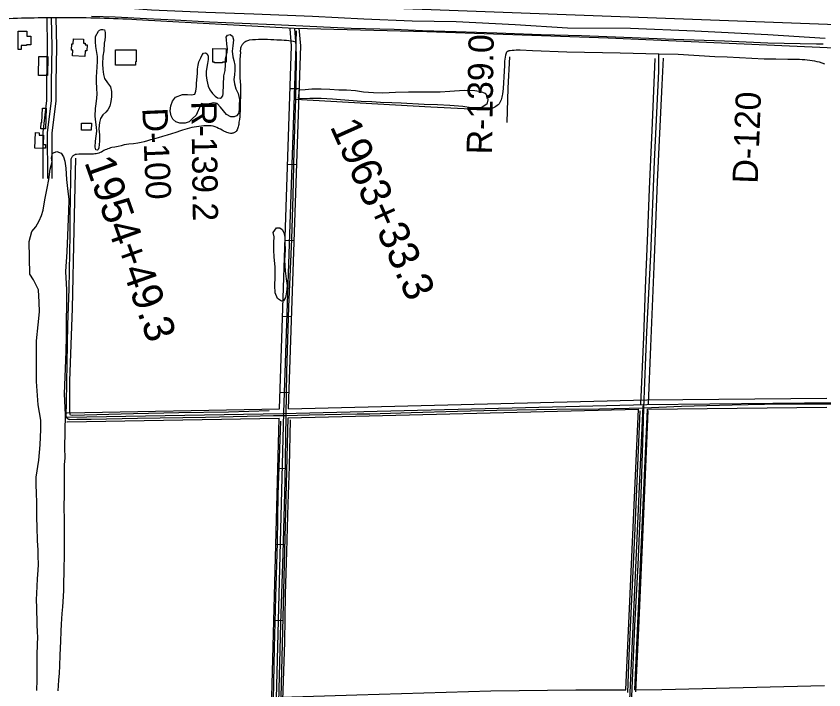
# Model space of a CAD drawing. Extents: x 3508733 to 3546731, y 546897 to 572481.
# Drawn here: x 3519217 to 3521873, y 561066 to 563281 of the extents above; entities that cross this region are included whole.
import ezdxf

# ---------------------------------------------------------------- set-up
doc = ezdxf.new("R2010")
doc.units = 0
for name, color, linetype in [('V-BLDG-OTLN', 7, 'Continuous'), ('V-DTCH-CNTR', 7, 'Continuous'), ('V-LEVE-TOET', 7, 'Continuous'), ('V-RIVR-RANG-IDEN', 7, 'Continuous'), ('V-ROAD-CNTR', 7, 'Continuous'), ('V-SITE-VEGE', 7, 'Continuous'), ('V-SURV-IDEN', 7, 'Continuous'), ('V-SURV-LINE', 7, 'Continuous'), ('V-TOPO-SHOR', 7, 'Continuous')]:
    doc.layers.add(name, color=color, linetype=linetype)

msp = doc.modelspace()

# ---------------------------------------------------------------- linework, layer by layer
at = {"layer": 'V-BLDG-OTLN'}
for points in [[(3519223.6, 563232.1), (3519252.1, 563232.1), (3519252.1, 563215.9), (3519265.8, 563215.9), (3519265.9, 563186.9), (3519251.6, 563186.8), (3519251.6, 563184.8), (3519233.9, 563184.7), (3519233.9, 563171.9), (3519223.7, 563171.9)], [(3519405.9, 563207.3), (3519438.8, 563205.9), (3519438.3, 563192.5), (3519444.3, 563192.3), (3519444.1, 563187.3), (3519450.4, 563187.1), (3519449.6, 563167.4), (3519443.8, 563167.6), (3519443, 563148.8), (3519402.9, 563150.4), (3519403.7, 563169.1), (3519399.4, 563169.3), (3519400.3, 563190.6), (3519405.2, 563190.4)], [(3519544.4, 563170.9), (3519611.7, 563170.9), (3519611.7, 563130.9), (3519609.8, 563130.9), (3519609.8, 563120.7), (3519544.4, 563120.7)], [(3519864.6, 563174.7), (3519908.4, 563174.2), (3519907.9, 563130.1), (3519896.1, 563130.2), (3519896.1, 563127.5), (3519869.2, 563127.8), (3519869.2, 563130.3), (3519864.1, 563130.4)], [(3519321.8, 563148.4), (3519320.7, 563086.2), (3519290.7, 563086.7), (3519291.8, 563148.9)], [(3519316.5, 562978.3), (3519314.1, 562910.8), (3519298.5, 562911.3), (3519299.2, 562931.6), (3519301.9, 562931.5), (3519303.5, 562978.7)], [(3519464.4, 562906.3), (3519432.2, 562906.7), (3519432.5, 562929.5), (3519464.7, 562929.1)], [(3519307.6, 562890.1), (3519306.7, 562859.1), (3519313.7, 562858.9), (3519313.4, 562847.1), (3519307.2, 562847.2), (3519307.2, 562846.1), (3519278.9, 562847), (3519280.5, 562898.2), (3519293.5, 562897.8), (3519293.3, 562890.5)]]:
    msp.add_lwpolyline(points, close=True, dxfattribs=at)
at = {"layer": 'V-DTCH-CNTR'}
for points in [[(3520138.2, 563233.1), (3520137.4, 563196.2), (3520138.4, 563133), (3520135.5, 563007.3)], [(3520137.4, 563196.2), (3520129.6, 563197.7), (3520121.8, 563199), (3520114, 563200.1), (3520106.1, 563200.9), (3520098.2, 563201.6), (3520090.4, 563202.1), (3520082.4, 563202.4), (3520074.5, 563202.4), (3520064.5, 563203.3), (3520054.5, 563204), (3520044.4, 563204.4), (3520034.3, 563204.6), (3520024.2, 563204.6), (3520014.2, 563204.3), (3520004.1, 563203.8), (3519994.1, 563203.1), (3519984, 563202.1), (3519981, 563201.3), (3519978.1, 563200.3), (3519975.2, 563199.1), (3519972.5, 563197.7), (3519969.8, 563196.1), (3519967.3, 563194.3), (3519964.9, 563192.3), (3519963, 563190.4), (3519961.3, 563188.3), (3519959.8, 563186.1), (3519958.5, 563183.8), (3519957.3, 563181.4), (3519956.3, 563178.9), (3519955.6, 563176.3), (3519955, 563173.7), (3519954.6, 563171.1), (3519954.4, 563168.4), (3519954.4, 563165.8), (3519954.7, 563163.1), (3519953.8, 563151), (3519953.2, 563138.9), (3519952.8, 563126.7), (3519952.5, 563114.6), (3519952.5, 563102.5), (3519952.7, 563090.3), (3519953.2, 563078.2), (3519953.8, 563066.1), (3519954.6, 563053.9), (3519955, 563038.1)], [(3521877, 563123.7), (3521868.3, 563126.7), (3521859.5, 563129.5), (3521851.4, 563131.4), (3521843.3, 563133.1), (3521835.1, 563134.5), (3521826.9, 563135.7), (3521818.7, 563136.7), (3521810.4, 563137.4), (3521802.2, 563138), (3521793.9, 563138.3), (3521755, 563138.9), (3521716.1, 563139.5), (3521677.3, 563139.9), (3521636.7, 563142.2), (3521596, 563144.3), (3521555.4, 563146.1), (3521514.7, 563147.7), (3521394.8, 563154.8), (3521331.3, 563155.9), (3521203.7, 563159.1), (3521027.9, 563162.9), (3520915.8, 563167.1), (3520874.8, 563169.2), (3520868.1, 563169.3), (3520861.4, 563169.3), (3520854.7, 563168.9), (3520848.1, 563168.3), (3520841.4, 563167.4), (3520839.6, 563167.3), (3520837.9, 563166.9), (3520836.2, 563166.4), (3520834.6, 563165.7), (3520833, 563164.7), (3520831.6, 563163.6), (3520830.4, 563162.4), (3520829.2, 563161), (3520828.3, 563159.4), (3520826.8, 563152.8), (3520825.5, 563146.2), (3520824.5, 563139.5), (3520823.8, 563132.8), (3520823.3, 563126), (3520823.1, 563119.2), (3520822.4, 563100.4), (3520821.4, 563081.5), (3520820.1, 563062.6), (3520818.6, 563043.8), (3520816.9, 563025), (3520816, 563020.2), (3520814.8, 563015.4), (3520813.4, 563010.7), (3520811.8, 563006.1), (3520809.9, 563001.5)], [(3521200.8, 560109.6), (3521206.1, 560234.8), (3521216.6, 560444), (3521225.9, 560642.9), (3521237.8, 560889.6), (3521242.3, 561044), (3521252.2, 561275.9), (3521262.4, 561476.9), (3521272.7, 561708.7), (3521279.4, 561913.5), (3521281.7, 561993.5), (3521291.8, 562243.4), (3521304.1, 562496.8), (3521316.7, 562803), (3521330.9, 563100.5), (3521331.3, 563155.9)], [(3519955, 563038.1), (3519954.3, 562978.7), (3519953.9, 562969.4), (3519953.4, 562960.2), (3519952.5, 562950.9), (3519951.5, 562941.7), (3519950.2, 562932.5), (3519949.9, 562928.8), (3519949.4, 562925.1), (3519948.7, 562921.4), (3519947.8, 562917.8), (3519946.7, 562914.3), (3519945.3, 562910.8), (3519943.8, 562907.4), (3519942, 562904.1), (3519940.6, 562902.4), (3519939, 562900.9), (3519937.2, 562899.6), (3519935.4, 562898.4), (3519933.4, 562897.4), (3519931.3, 562896.7), (3519929.2, 562896.1), (3519927, 562895.7), (3519924.8, 562895.6), (3519922.6, 562895.6), (3519918.4, 562896.5), (3519914.3, 562897.6), (3519910.2, 562899), (3519906.2, 562900.6), (3519902.3, 562902.4), (3519898.5, 562904.5), (3519894.8, 562906.8), (3519889.1, 562909.7), (3519883.3, 562912.4), (3519877.4, 562914.9), (3519871.4, 562917.1), (3519865.4, 562919.2), (3519859.2, 562921), (3519851, 562921), (3519842.8, 562920.9), (3519834.6, 562920.4), (3519826.4, 562919.8), (3519818.3, 562918.9), (3519810.5, 562917.9), (3519802.7, 562916.6), (3519795.1, 562915.1), (3519787.4, 562913.3), (3519779.8, 562911.3), (3519772.3, 562909.1), (3519764.9, 562906.6), (3519757.5, 562903.8), (3519743, 562898.9), (3519728.4, 562894.2), (3519713.8, 562889.6), (3519699.1, 562885.3), (3519684.3, 562881.2), (3519669.5, 562877.3)], [(3520135.5, 563007.3), (3520134.9, 562981.2), (3520130.4, 562840.1), (3520126.7, 562690.3), (3520122.7, 562548), (3520113.1, 562325.6), (3520106.9, 562112), (3520103.9, 561967.9), (3520100.4, 561752.6), (3520094.1, 561512.8), (3520087, 561283.7), (3520079.7, 561024)], [(3520770.5, 562973.9), (3520756.9, 562973.6), (3520581.2, 562981.7), (3520135.5, 563007.3)], [(3520809.9, 563001.5), (3520807.8, 562997.1), (3520805.5, 562992.7), (3520802.2, 562989.9), (3520798.8, 562987.1), (3520795.2, 562984.6), (3520791.5, 562982.3), (3520787.6, 562980.2), (3520783.7, 562978.3), (3520779.7, 562976.7), (3520775.5, 562975.2), (3520771.3, 562974), (3520770.5, 562973.9)], [(3519669.5, 562877.3), (3519659.3, 562874.1), (3519649, 562871.1), (3519638.7, 562868.4), (3519628.3, 562865.9), (3519617.8, 562863.7), (3519602.9, 562862), (3519587.9, 562860), (3519573.1, 562857.8), (3519562.8, 562855.2), (3519552.5, 562852.9), (3519542.1, 562850.8), (3519531.7, 562849), (3519527.2, 562847.9), (3519522.8, 562846.6), (3519518.5, 562845), (3519514.2, 562843.3), (3519510.1, 562841.3), (3519506, 562839.2), (3519502.1, 562836.8), (3519498.2, 562834.2), (3519493.9, 562832.6), (3519489.5, 562831.1), (3519485, 562829.9), (3519480.5, 562828.9), (3519475.9, 562828.1), (3519471.3, 562827.6), (3519466.7, 562827.2), (3519462, 562827.1), (3519457.4, 562827.3), (3519452.7, 562827.7), (3519445.4, 562828)], [(3519415.9, 562826.5), (3519413.9, 562826.4), (3519411.8, 562826), (3519409.8, 562825.4), (3519407.9, 562824.6), (3519406.1, 562823.6), (3519404.5, 562822.3), (3519402.9, 562820.8), (3519401.4, 562819.1), (3519400.2, 562817.3), (3519399.1, 562815.4), (3519398.2, 562813.4), (3519397.5, 562811.3), (3519397.1, 562809.1), (3519396.8, 562806.9), (3519395.7, 562745.2), (3519394.8, 562683.5), (3519394.1, 562621.8), (3519393.5, 562562.5), (3519392.6, 562503.3), (3519391.5, 562444), (3519390.1, 562384.8), (3519388.5, 562325.5), (3519386.7, 562266.3)], [(3519445.4, 562828), (3519438, 562828), (3519430.6, 562827.8), (3519423.3, 562827.3), (3519415.9, 562826.5)], [(3519386.7, 562266.3), (3519381.6, 562012.3), (3519380.9, 561966), (3519381.3, 561964.3), (3519382, 561962.7), (3519382.9, 561961.2), (3519383.9, 561959.9), (3519385.1, 561958.6), (3519386.5, 561957.6), (3519388, 561956.7), (3519389.5, 561956), (3519391.2, 561955.5), (3519392.9, 561955.3), (3519416.6, 561955.7), (3519440.4, 561955.8), (3519464.1, 561955.6), (3519615.9, 561959.2), (3519839.6, 561962.7), (3519977.4, 561965.6), (3520063.3, 561968.5), (3520103.9, 561967.9)], [(3520103.9, 561967.9), (3520181.4, 561970.3), (3520338.6, 561973.6), (3520380.4, 561973.3), (3520515.9, 561977.7), (3520668.2, 561982), (3520798.5, 561985.6), (3520993.9, 561989.2), (3521135.9, 561989.5), (3521281.7, 561993.5), (3521405.1, 561999.2), (3521571.5, 562003.1), (3521731.1, 562006.2), (3521902.6, 562006.1)]]:
    msp.add_lwpolyline(points, dxfattribs=at)
at = {"layer": 'V-LEVE-TOET'}
msp.add_lwpolyline([(3521877.3, 563208), (3521689.6, 563219.8), (3521449.1, 563231.9), (3521238, 563240.3), (3521030.7, 563241.6), (3520858.9, 563253.2), (3520664.7, 563263.2), (3520520, 563264.6), (3520360.8, 563271.9), (3520191.5, 563280.1), (3519999.1, 563288), (3519841.5, 563293.5), (3519662, 563301.5), (3519578.4, 563307.7), (3519455.1, 563312.4), (3519315.4, 563322.4), (3519199.5, 563317.2)], dxfattribs=at)
at = {"layer": 'V-ROAD-CNTR'}
for p, q in [((3520118.4, 563043.9), (3520148.4, 563042.9)), ((3520110, 562794.1), (3520140, 562793.1)), ((3520101.7, 562544.2), (3520131.7, 562543.2)), ((3520093.3, 562294.3), (3520123.3, 562293.3)), ((3520084.9, 562044.5), (3520114.9, 562043.5)), ((3520078, 561794.5), (3520108, 561793.7)), ((3520071.6, 561544.5), (3520101.6, 561543.8)), ((3520065.2, 561294.6), (3520095.2, 561293.9))]:
    msp.add_line(p, q, dxfattribs=at)
for points in [[(3519317.9, 563275.5), (3519319.9, 563181.1), (3519317.6, 563062.2), (3519317.4, 563003.7), (3519304.7, 562899.4), (3519305.1, 562747.6)], [(3519332.9, 563275.8), (3519334.9, 563181.2), (3519332.6, 563062.1), (3519332.4, 563002.8), (3519319.7, 562898.5), (3519320.1, 562747.6)], [(3519347.9, 563276.1), (3519349.9, 563181.2), (3519347.6, 563061.9), (3519347.4, 563001.9), (3519334.7, 562897.6), (3519335.1, 562747.7)], [(3523486.8, 563119.6), (3523364.6, 563119.4), (3522668.4, 563145.9), (3522135.8, 563169), (3521909.5, 563175.7), (3521163.8, 563208.5), (3520567.9, 563230), (3520131.3, 563241.1), (3519612.9, 563269.3)], [(3519967.4, 557245.9), (3519997.9, 558160.3), (3520022.3, 559134.5), (3520051.5, 560082.9), (3520073.6, 561037.4), (3520097.7, 561978.1), (3520138.1, 563183.8), (3520133.3, 563241.1)], [(3520083.1, 561989.6), (3520123.1, 563183.4), (3520118.4, 563239.8)], [(3520113.2, 561990.3), (3520153.1, 563184.2), (3520148.2, 563242.3)], [(3519383.9, 561962.3), (3519385.1, 561962.4), (3520094.7, 561974.8), (3521291.5, 562004.2), (3521912.4, 562010.4), (3522605.1, 562030.9)], [(3520113.2, 561990.3), (3521291.2, 562019.2), (3521883.4, 562025.1)], [(3521192.5, 560127.6), (3521202.3, 560314.9), (3521236.7, 561056.2), (3521279.5, 562000.2)], [(3519383.4, 561977.3), (3519384.7, 561977.3), (3520083.1, 561989.6)], [(3520112.3, 561960.3), (3521263.9, 561988.5)], [(3521222.2, 561066.2), (3521263.9, 561988.5)], [(3521252.2, 561066.3), (3521294, 561989.2)], [(3521294, 561989.2), (3521883.2, 561995.1)], [(3519384.3, 561947.3), (3519385.4, 561947.4), (3520082.3, 561959.6)], [(3520058.7, 561042.1), (3520082.3, 561959.6)], [(3520088.7, 561042.2), (3520112.3, 561960.3)], [(3521252.2, 561066.3), (3521340.4, 561066.5), (3521875.7, 561080.2)], [(3520088.7, 561042.2), (3520337.5, 561049.5), (3520778.3, 561062.5), (3521058, 561065.7), (3521222.2, 561066.2)]]:
    msp.add_lwpolyline(points, dxfattribs=at)
for centre, radius, start, end in [((3519354.7, 558597.9), 4677.9, 89.7771, 92.4746), ((3519394.4, 559639.2), 3636.6, 86.5559, 90.338)]:
    msp.add_arc(centre, radius, start, end, dxfattribs=at)
at = {"layer": 'V-SITE-VEGE'}
for points in [[(3519487.7, 563231.8), (3519491.6, 563235.6), (3519497.4, 563237.5), (3519502.5, 563237.9), (3519507.6, 563235.9), (3519509.9, 563227.9), (3519510, 563214.4), (3519508.6, 563202.1), (3519507.3, 563192), (3519505.3, 563167.8), (3519502.5, 563150), (3519501, 563123.9), (3519502.4, 563106.5), (3519504.9, 563089.4), (3519508.4, 563076.5), (3519517.6, 563062.4), (3519527.4, 563049.3), (3519530.8, 563033.8), (3519530.4, 563016.1), (3519528.8, 563000.2), (3519525, 562985.5), (3519518.8, 562973.5), (3519512.2, 562965.2), (3519502.7, 562956.3), (3519495, 562945.3), (3519491.3, 562931.3), (3519489.8, 562910.3), (3519491, 562890.8), (3519492, 562870.2), (3519489.3, 562848.5), (3519487.1, 562842.5), (3519484.7, 562840.4), (3519479.6, 562841.2), (3519477.1, 562850.8), (3519477.8, 562870.6), (3519483, 562902.7), (3519481.4, 562916.7), (3519479.2, 562932.9), (3519477.5, 562952.3), (3519477.8, 562977.4), (3519480.4, 562992.8), (3519483.2, 563012.1), (3519483.6, 563025.4), (3519483.1, 563043.7), (3519481.7, 563066.2), (3519482.1, 563082.1), (3519483, 563097.6), (3519485.3, 563131.9), (3519484.6, 563148.3), (3519481.9, 563168.1), (3519479.6, 563181.2), (3519477.9, 563196.9), (3519478.3, 563214.8)], [(3519823.3, 562988.5), (3519809, 562955.9), (3519796.7, 562943.9), (3519785.8, 562934), (3519773.7, 562929.6), (3519755.1, 562929.7), (3519742.2, 562934.1), (3519732.1, 562942.1), (3519727.1, 562953.1), (3519723.4, 562969.7), (3519726.3, 562986.3), (3519731.6, 563001.8), (3519741.7, 563014.8), (3519764, 563023.6), (3519780.7, 563023.2), (3519793.8, 563022.4), (3519804.7, 563024.9), (3519808.3, 563034.2), (3519809.9, 563050.3), (3519810.4, 563060.9), (3519813.5, 563093.1), (3519814.2, 563107.2), (3519815.4, 563119.7), (3519818, 563130.9), (3519824.3, 563144.8), (3519828.7, 563153.7), (3519833.9, 563159.8), (3519839.8, 563160.9), (3519845.4, 563157.1), (3519849.3, 563149.4), (3519849.3, 563138.4), (3519847, 563125.3), (3519844.3, 563113.1), (3519842.2, 563099.6), (3519842.3, 563085.7), (3519844.6, 563071.3), (3519846.7, 563060.5), (3519848.7, 563051.6), (3519853.9, 563039), (3519863, 563027.5), (3519872.1, 563018.6), (3519879.7, 563013.2), (3519889.3, 563011.3), (3519892.7, 563013.8), (3519896.7, 563019.5), (3519898.1, 563027.5), (3519900.4, 563085.4), (3519904.7, 563102.4), (3519905.5, 563121.8), (3519905.7, 563140.3), (3519910.9, 563162.4), (3519912, 563174.4), (3519910.2, 563189.5), (3519909, 563204.8), (3519908.5, 563211.9), (3519911.9, 563219.1), (3519921.1, 563221.4), (3519928.9, 563216), (3519932.3, 563203.2), (3519929.5, 563183.8), (3519927.8, 563166.7), (3519930.3, 563148.1), (3519933.1, 563135.9), (3519936.3, 563120.7), (3519936.7, 563103.4), (3519935.3, 563088.9), (3519933.6, 563073), (3519935, 563059.3), (3519940.3, 563042.5), (3519947, 563027.2), (3519951.9, 563006.8), (3519950.8, 562989.9), (3519950.6, 562974.8), (3519948.4, 562961), (3519941.6, 562953.2), (3519933.9, 562949.8), (3519922.9, 562949.9), (3519909.1, 562957.9), (3519889.9, 562981.9), (3519877.9, 562994), (3519867.9, 562996.5), (3519851.8, 562992.9), (3519839.8, 562991.9), (3519830.6, 562993.2), (3519826.5, 562993.6)], [(3520149.1, 563039.2), (3520167.4, 563040.5), (3520189.6, 563042.4), (3520220.2, 563042.6), (3520249.4, 563040.7), (3520278.5, 563039.2), (3520303.4, 563038.9), (3520332.8, 563036.8), (3520359.1, 563032.8), (3520392.8, 563030), (3520423.2, 563029.7), (3520464.6, 563031.8), (3520507.4, 563033), (3520543.9, 563032.4), (3520611.5, 563032.8), (3520643.5, 563034.4), (3520690.8, 563037.8), (3520725.5, 563036.8), (3520745.5, 563033.4), (3520758.6, 563028), (3520766.2, 563019.3), (3520769, 563005.7), (3520765.3, 562992), (3520747.1, 562980.2), (3520713.9, 562980.2), (3520685.9, 562983.7), (3520643.9, 562987.7), (3520602.9, 562989.6), (3520559.2, 562990.3), (3520483.5, 562995), (3520452.5, 562996), (3520416, 562997.4), (3520387.1, 562999.1), (3520352, 563000.5), (3520325.8, 563003.3), (3520284.4, 563006.2), (3520257.7, 563008.2), (3520220.6, 563010.2), (3520183.3, 563010.7), (3520160, 563009.8), (3520146.1, 563010.1)], [(3520062.5, 562569.9), (3520073.1, 562585), (3520085, 562585.5), (3520092.6, 562579.5), (3520097.6, 562570.4), (3520100.8, 562554.5), (3520100.8, 562536), (3520101.7, 562512.3), (3520099.7, 562477.4), (3520101.7, 562444), (3520105.7, 562417.4), (3520108.4, 562395.8), (3520106, 562373.3), (3520102.8, 562356.6), (3520096, 562345.5), (3520089.7, 562343.6), (3520077.1, 562352.8), (3520069.4, 562371.9), (3520067.9, 562395.7), (3520069, 562423.4), (3520068.8, 562456.7), (3520065.7, 562488.2), (3520064.6, 562512.9), (3520064.5, 562536.7), (3520065.8, 562555.1)]]:
    msp.add_lwpolyline(points, close=True, dxfattribs=at)
for points in [[(3519285.4, 561063.1), (3519286.3, 561099), (3519286.1, 561144.3), (3519286.3, 561176.4), (3519287.9, 561219.8), (3519288.2, 561235.7), (3519287.7, 561260.3), (3519286.4, 561276.5), (3519286.3, 561301.4), (3519285.4, 561318), (3519284.9, 561335), (3519284.8, 561363.4), (3519285, 561382.6), (3519287.8, 561430.6), (3519289.5, 561459), (3519290.5, 561477.8), (3519290.3, 561506.2), (3519289.8, 561525.4), (3519287.8, 561556.4), (3519286.7, 561601), (3519286.7, 561608.5), (3519285.8, 561624.8), (3519285.6, 561672.7), (3519285.1, 561690.8), (3519284.2, 561703.7), (3519284.1, 561721.4), (3519283.7, 561730.9), (3519283.6, 561751.7), (3519282.8, 561761.5), (3519282.7, 561765.6), (3519292, 561821.4), (3519296.5, 561871.2), (3519298.8, 561921.5), (3519298.8, 561952.7), (3519290.1, 562002.6), (3519284.6, 562080), (3519284.5, 562213.2), (3519289.8, 562265.7), (3519293.7, 562309.2), (3519293, 562340.7), (3519290.4, 562381.4), (3519274.7, 562414.1), (3519262.5, 562432.7), (3519260.2, 562540.6), (3519269, 562572.7), (3519281.6, 562588.4), (3519293.6, 562607.7), (3519300.2, 562625.6), (3519305.7, 562643), (3519311.6, 562677.5), (3519314.6, 562694.1), (3519319.5, 562715.6), (3519324.5, 562743.8), (3519328.9, 562777.7), (3519336, 562802.3), (3519333.2, 562813.9), (3519337.3, 562830.4), (3519350.7, 562836.5), (3519365.4, 562830.4), (3519373.1, 562819.2), (3519377.2, 562805), (3519380.5, 562781), (3519382.4, 562744.7), (3519386.4, 562714.7), (3519390.1, 562678.7), (3519389.5, 562640.7), (3519383.8, 562506.4), (3519380.1, 562441.5), (3519382.6, 562380.9), (3519382, 562228.7), (3519380.6, 562178.1), (3519375.1, 562039.3), (3519379, 561970.4), (3519376.4, 561862), (3519377, 561828.7), (3519375.7, 561805.3), (3519375.1, 561748.1), (3519375.3, 561703.9), (3519375, 561694.8), (3519374.7, 561681.2), (3519374, 561671), (3519374.1, 561652.5), (3519375, 561638.9), (3519375.6, 561530.1), (3519375.1, 561496.5), (3519374.1, 561475), (3519373.9, 561444.8), (3519373.2, 561424.7), (3519373.1, 561393.4), (3519372, 561372.6), (3519369.6, 561339.3), (3519367.5, 561316.3), (3519365, 561281.5), (3519364.4, 561259.2), (3519362.7, 561225.6), (3519361.7, 561202.6)], [(3519361.7, 561202.6), (3519361.5, 561179.5), (3519360.2, 561144.4), (3519358.8, 561120.2), (3519357.1, 561097.9), (3519354.6, 561062.8)]]:
    msp.add_lwpolyline(points, dxfattribs=at)
at = {"layer": 'V-SURV-LINE'}
msp.add_lwpolyline([(3523634.8, 563189.5), (3520196.3, 563316.1)], dxfattribs=at)
at = {"layer": 'V-TOPO-SHOR'}
for points in [[(3519465.6, 563281.1), (3519542.5, 563278.6), (3519645.6, 563273.7), (3519740.5, 563269.7), (3519853.6, 563263.1), (3519960.3, 563258.3), (3520067.2, 563254), (3520183, 563248.7), (3520319.3, 563242), (3520460.9, 563239), (3520553.7, 563234.3), (3520664.7, 563230.8), (3520797.8, 563226.7), (3520944.3, 563220.7), (3521076.1, 563217.7), (3521215.3, 563212.3), (3521380.6, 563205.9), (3521547.1, 563200.3), (3521689.8, 563193.6), (3521849.3, 563190), (3521871.2, 563190.5)], [(3520840.1, 563147.7), (3520834.2, 563044.3), (3520830.8, 562931.6)], [(3521297, 562005.9), (3521304.4, 562195.3), (3521315.1, 562458), (3521326.7, 562736.4), (3521341.4, 563055.3), (3521346.5, 563143.4)], [(3521318.1, 563142), (3521309.3, 562930), (3521299.2, 562712.8), (3521292.5, 562542.4), (3521286.4, 562386.8), (3521280.1, 562226.8), (3521270.3, 562003.7)], [(3520049.6, 561982.9), (3519916.1, 561978.9), (3519752.1, 561976.3), (3519602.8, 561973.3), (3519402, 561967.7), (3519396.5, 561969.5), (3519394.5, 561971.7), (3519393.4, 561979.4), (3519393.6, 562081.6), (3519402.5, 562319.9), (3519408.4, 562578.7), (3519413.1, 562814.5)], [(3521267.9, 561982.9), (3521251.2, 561572.7), (3521232.6, 561178.6), (3521228.1, 561056.9)], [(3521255.1, 561059.4), (3521265, 561268.8), (3521278.6, 561567.7), (3521291.6, 561875.4), (3521296.1, 561984.1)], [(3520063.3, 561031.5), (3520067, 561203.9), (3520071.5, 561370), (3520076.7, 561550.5), (3520079.3, 561708.5), (3520088.2, 561949)], [(3520118, 561953.8), (3520115.2, 561800.6), (3520110.9, 561677.5), (3520106.7, 561519.8), (3520101.9, 561380.7), (3520099.3, 561222.2), (3520093, 561032.3)]]:
    msp.add_lwpolyline(points, dxfattribs=at)

# ---------------------------------------------------------------- texts
at = {"layer": 'V-RIVR-RANG-IDEN'}
for s, rotation, p in [('R-139.0', 89.0406, (3520781.7, 562826.3)), ('D-120', 87.8253, (3521655.7, 562729.5)), ('R-139.2', 270.7523, (3519793.4, 563001.3)), ('D-100', 272.4033, (3519632.2, 562978.5))]:
    msp.add_text(s, height=83, rotation=rotation, dxfattribs=at).set_placement(p)
at = {"layer": 'V-SURV-IDEN'}
for s, rotation, p in [('1963+33.3', 294.0784, (3520248.1, 562918.8)), ('1954+49.3', 289.4518, (3519440.8, 562801.5))]:
    msp.add_text(s, height=100, rotation=rotation, dxfattribs=at).set_placement(p)

doc.saveas('drawing.dxf')
